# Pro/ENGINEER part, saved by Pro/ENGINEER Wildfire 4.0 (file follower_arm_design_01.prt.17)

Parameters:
  METRIC = "NO"

Other parameters: PITCH, DRILL_DIAMETER, THREAD_DIAMETER, THREADS_PER_INCH, THREAD_DEPTH, THREAD_LENGTH, DRILL_POINT_ANGLE, DRILL_DEPTH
